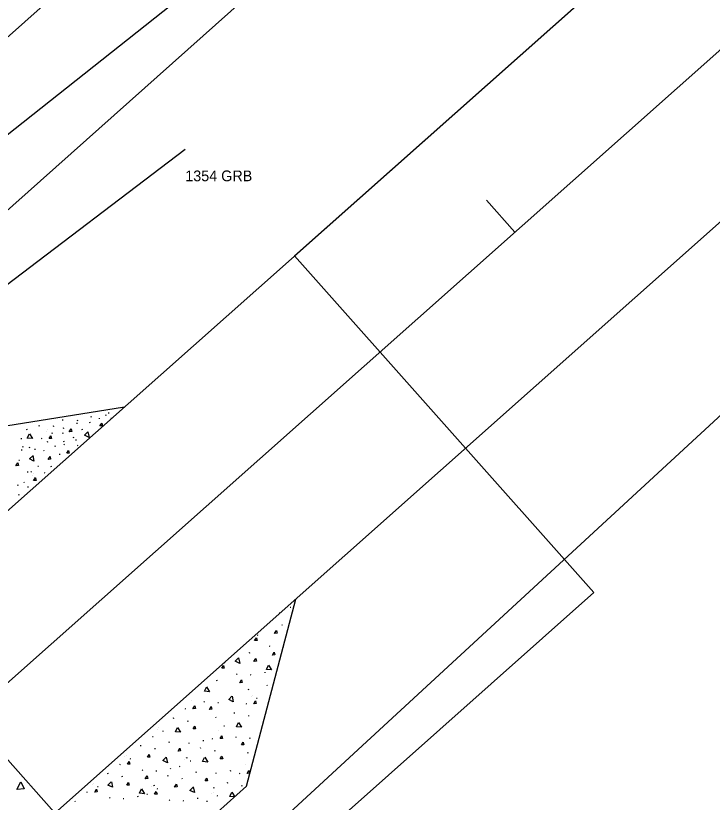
# Model space of a CAD drawing. Extents: x 50001 to 56005, y 49075 to 53926.
# Drawn here: x 53943.1 to 54007.9, y 51854.2 to 51927.5 of the extents above; entities that cross this region are included whole.
import ezdxf

# ---------------------------------------------------------------- set-up
doc = ezdxf.new("R2010")
doc.units = 0
for name, color, linetype in [('Level 1', 7, 'Continuous'), ('Level 11', 7, 'Continuous'), ('Level 12', 7, 'Continuous'), ('Level 15', 7, 'Continuous'), ('Level 18', 7, 'Continuous'), ('Level 19', 7, 'Continuous'), ('Level 20', 7, 'Continuous'), ('Level 3', 7, 'Continuous'), ('Level 57', 7, 'Continuous'), ('Level 7', 7, 'Continuous'), ('Level 8', 7, 'Continuous')]:
    doc.layers.add(name, color=color, linetype=linetype)

msp = doc.modelspace()

# ---------------------------------------------------------------- linework, layer by layer
at = {"layer": 'Level 1'}
for p, q in [((52544.807, 50683.302), (55534.583, 53340.862)), ((52714.147, 50773.616), (54181.768, 52078.16))]:
    msp.add_line(p, q, dxfattribs=at)
at = {"layer": 'Level 11'}
msp.add_line((53944.235, 51830.768), (54450.301, 52297.6), dxfattribs=at)
at = {"layer": 'Level 12'}
for p, q in [((55279.532, 53069.998), (53969.027, 51905.114)), ((53996.93, 51873.722), (53969.027, 51905.114)), ((53681.554, 51593.39), (53996.93, 51873.722))]:
    msp.add_line(p, q, dxfattribs=at)
at = {"layer": 'Level 15'}
msp.add_line((53924.129, 51878.584), (53953.361, 51845.698), dxfattribs=at)
msp.add_lwpolyline([(53943.175, 51855.366), (53943.549, 51856.073), (53943.841, 51855.421), (53943.189, 51855.366)], dxfattribs=at)
at = {"layer": 'Level 18'}
msp.add_line((53926.024, 51903.545), (53965.282, 51934.64), dxfattribs=at)
at = {"layer": 'Level 19'}
for p, q in [((52714.147, 50773.616), (54181.768, 52078.16)), ((53989.569, 51907.317), (53986.911, 51910.307))]:
    msp.add_line(p, q, dxfattribs=at)
at = {"layer": 'Level 20'}
for p, q in [((53930.772, 51871.11), (54173.796, 52087.129)), ((53946.717, 51853.172), (54189.74, 52069.191))]:
    msp.add_line(p, q, dxfattribs=at)
at = {"layer": 'Level 3'}
msp.add_line((53898.742, 51870.567), (54083.389, 52035.124), dxfattribs=at)
at = {"layer": 'Level 7'}
msp.add_line((53922.854, 51887.665), (53958.852, 51915.059), dxfattribs=at)
at = {"layer": 'Level 8'}
for p, q in [((53935.625, 51888.219), (53953.195, 51891.04)), ((53947.407, 51889.839), (53947.431, 51889.752)), ((53948.779, 51889.828), (53948.803, 51889.74)), ((53950.065, 51890.146), (53950.09, 51890.058)), ((53950.818, 51889.99), (53950.842, 51889.902)), ((53951.433, 51890.314), (53951.458, 51890.226)), ((53951.692, 51890.508), (53951.717, 51890.42)), ((53951.98, 51889.935), (53951.916, 51889.955)), ((53945.205, 51889.332), (53945.23, 51889.244)), ((53946.545, 51889.277), (53946.569, 51889.189)), ((53947.471, 51889.1), (53947.496, 51889.012)), ((53948.738, 51889.545), (53948.763, 51889.458)), ((53949.944, 51889.633), (53949.968, 51889.545)), ((53944.059, 51888.987), (53944.083, 51888.9)), ((53945.937, 51888.773), (53945.937, 51888.773)), ((53946.066, 51888.879), (53946.066, 51888.879)), ((53946.503, 51888.557), (53946.439, 51888.576)), ((53947.419, 51888.629), (53947.443, 51888.541)), ((53949.232, 51888.985), (53949.256, 51888.897)), ((53943.554, 51888.096), (53943.578, 51888.008)), ((53945.519, 51888.053), (53945.456, 51888.072)), ((53945.994, 51887.819), (53946.019, 51887.731)), ((53947.516, 51887.851), (53947.54, 51887.763)), ((53948.422, 51888.24), (53948.447, 51888.152)), ((53948.649, 51887.981), (53948.673, 51887.893)), ((53943.586, 51887.059), (53943.611, 51886.971)), ((53943.696, 51887.365), (53943.72, 51887.277)), ((53944.317, 51887.299), (53944.341, 51887.211)), ((53944.829, 51887.106), (53944.853, 51887.018)), ((53945.649, 51887.005), (53945.673, 51886.917)), ((53946.707, 51887.43), (53946.731, 51887.342)), ((53947.604, 51887.486), (53947.544, 51887.545)), ((53948.89, 51887.395), (53948.826, 51887.414)), ((53947.127, 51886.652), (53947.152, 51886.564)), ((53943.413, 51886.016), (53943.349, 51886.035)), ((53945.106, 51885.514), (53945.17, 51885.497)), ((53946.378, 51885.404), (53946.351, 51885.491)), ((53944.139, 51884.98), (53944.204, 51884.962)), ((53944.515, 51884.945), (53944.455, 51885.004)), ((53944.711, 51884.781), (53944.711, 51884.781)), ((53945.801, 51884.854), (53945.737, 51884.873)), ((53943.822, 51884.056), (53943.847, 51883.968)), ((53944.586, 51884.671), (53944.586, 51884.671)), ((53944.878, 51884.372), (53944.851, 51884.459)), ((53943.276, 51883.669), (53943.249, 51883.756)), ((53944.178, 51883.602), (53944.203, 51883.514)), ((53943.37, 51882.767), (53943.343, 51882.854)), ((53964.572, 51855.663), (53969.139, 51873.103)), ((53968.685, 51872.317), (53968.621, 51872.336)), ((53967.709, 51871.799), (53967.645, 51871.817)), ((53967.855, 51870.753), (53967.88, 51870.665)), ((53965.634, 51869.73), (53965.57, 51869.749)), ((53966.752, 51868.677), (53966.691, 51868.734)), ((53968.039, 51868.605), (53967.975, 51868.623)), ((53964.804, 51868.166), (53964.829, 51868.078)), ((53962.583, 51867.143), (53962.519, 51867.162)), ((53963.701, 51866.09), (53963.64, 51866.147)), ((53964.988, 51866.018), (53964.924, 51866.036)), ((53966.253, 51866.314), (53966.278, 51866.226)), ((53961.753, 51865.579), (53961.779, 51865.491)), ((53966.446, 51865.134), (53966.472, 51865.047)), ((53964.718, 51864.734), (53964.744, 51864.646)), ((53959.446, 51863.684), (53959.446, 51863.684)), ((53960.65, 51863.503), (53960.589, 51863.56)), ((53961.937, 51863.43), (53961.873, 51863.449)), ((53964.993, 51864.046), (53964.993, 51864.046)), ((53965.12, 51864.154), (53965.12, 51864.154)), ((53965.562, 51863.838), (53965.497, 51863.856)), ((53958.912, 51862.85), (53958.847, 51862.868)), ((53964.586, 51863.32), (53964.522, 51863.338)), ((53957.721, 51862.077), (53957.747, 51861.99)), ((53961.668, 51862.147), (53961.693, 51862.059)), ((53963.395, 51862.547), (53963.421, 51862.46)), ((53964.731, 51862.273), (53964.757, 51862.186)), ((53959.057, 51861.803), (53959.083, 51861.716)), ((53962.511, 51861.251), (53962.447, 51861.269)), ((53956.268, 51860.989), (53956.268, 51860.989)), ((53956.395, 51861.097), (53956.395, 51861.097)), ((53956.836, 51860.781), (53956.772, 51860.799)), ((53961.971, 51860.897), (53961.971, 51860.897)), ((53955.861, 51860.263), (53955.797, 51860.281)), ((53957.324, 51859.836), (53957.349, 51859.749)), ((53960.506, 51859.952), (53960.531, 51859.864)), ((53961.437, 51860.063), (53961.373, 51860.081)), ((53963.629, 51860.197), (53963.568, 51860.255)), ((53964.916, 51860.125), (53964.852, 51860.144)), ((53954.67, 51859.49), (53954.696, 51859.403)), ((53956.006, 51859.216), (53956.032, 51859.129)), ((53959.241, 51859.655), (53959.177, 51859.674)), ((53960.246, 51859.291), (53960.272, 51859.203)), ((53953.217, 51858.402), (53953.217, 51858.402)), ((53953.344, 51858.51), (53953.344, 51858.51)), ((53958.92, 51858.31), (53958.92, 51858.31)), ((53958.971, 51858.372), (53958.997, 51858.284)), ((53961.582, 51859.017), (53961.608, 51858.929)), ((53964.646, 51858.842), (53964.672, 51858.754)), ((53952.81, 51857.676), (53952.746, 51857.694)), ((53953.785, 51858.194), (53953.721, 51858.212)), ((53958.793, 51858.202), (53958.793, 51858.202)), ((53959.361, 51857.994), (53959.297, 51858.013)), ((53964.496, 51857.657), (53964.496, 51857.657)), ((53951.619, 51856.903), (53951.645, 51856.816)), ((53954.903, 51857.14), (53954.842, 51857.198)), ((53956.19, 51857.068), (53956.126, 51857.087)), ((53957.455, 51857.365), (53957.481, 51857.277)), ((53958.386, 51857.476), (53958.322, 51857.494)), ((53959.849, 51857.05), (53959.875, 51856.962)), ((53961.766, 51856.868), (53961.702, 51856.887)), ((53963.031, 51857.165), (53963.057, 51857.077)), ((53963.962, 51856.822), (53963.898, 51856.841)), ((53952.955, 51856.629), (53952.981, 51856.542)), ((53957.195, 51856.703), (53957.221, 51856.616)), ((53958.531, 51856.43), (53958.557, 51856.342)), ((53950.166, 51855.815), (53950.166, 51855.815)), ((53950.293, 51855.923), (53950.293, 51855.923)), ((53950.735, 51855.607), (53950.67, 51855.626)), ((53953.361, 51845.698), (53964.572, 51855.663)), ((53955.742, 51855.615), (53955.742, 51855.615)), ((53955.869, 51855.723), (53955.869, 51855.723)), ((53955.921, 51855.785), (53955.946, 51855.697)), ((53956.311, 51855.407), (53956.246, 51855.426)), ((53961.497, 51855.585), (53961.522, 51855.497)), ((53962.771, 51856.05), (53962.797, 51855.963)), ((53964.107, 51855.776), (53964.133, 51855.689)), ((53949.759, 51855.089), (53949.695, 51855.107)), ((53954.404, 51854.778), (53954.43, 51854.69)), ((53955.335, 51854.889), (53955.271, 51854.907)), ((53961.318, 51854.962), (53961.318, 51854.962)), ((53961.445, 51855.07), (53961.445, 51855.07)), ((53961.886, 51854.754), (53961.822, 51854.772)), ((53948.568, 51854.316), (53948.594, 51854.229)), ((53951.852, 51854.553), (53951.791, 51854.611)), ((53953.139, 51854.481), (53953.075, 51854.5)), ((53957.428, 51854.353), (53957.367, 51854.411)), ((53958.715, 51854.281), (53958.651, 51854.3)), ((53959.98, 51854.578), (53960.006, 51854.49)), ((53960.911, 51854.235), (53960.847, 51854.254))]:
    msp.add_line(p, q, dxfattribs=at)
for points in [[(53951.077, 51889.504), (53951.138, 51889.255), (53950.907, 51889.245), (53951.077, 51889.504)], [(53944.334, 51888.526), (53944.613, 51888.071), (53944.14, 51888.125), (53944.329, 51888.518)], [(53948.222, 51888.974), (53948.283, 51888.725), (53948.052, 51888.714), (53948.222, 51888.974)], [(53949.792, 51888.698), (53949.899, 51888.175), (53949.473, 51888.387), (53949.785, 51888.692)], [(53946.345, 51888.343), (53946.406, 51888.094), (53946.175, 51888.084), (53946.345, 51888.343)], [(53947.987, 51886.963), (53948.049, 51886.714), (53947.818, 51886.704), (53947.987, 51886.963)], [(53944.655, 51886.483), (53944.762, 51885.96), (53944.336, 51886.172), (53944.648, 51886.477)], [(53946.253, 51886.393), (53946.314, 51886.144), (53946.083, 51886.133), (53946.253, 51886.393)], [(53943.255, 51885.802), (53943.316, 51885.553), (53943.085, 51885.543), (53943.255, 51885.802)], [(53944.898, 51884.423), (53944.959, 51884.174), (53944.728, 51884.163), (53944.898, 51884.423)], [(53967.347, 51870.173), (53967.412, 51869.925), (53967.181, 51869.911), (53967.347, 51870.173)], [(53965.479, 51869.515), (53965.544, 51869.266), (53965.313, 51869.253), (53965.479, 51869.515)], [(53967.143, 51868.16), (53967.208, 51867.912), (53966.977, 51867.898), (53967.143, 51868.16)], [(53963.818, 51867.629), (53963.933, 51867.107), (53963.503, 51867.313), (53963.811, 51867.623)], [(53965.417, 51867.563), (53965.482, 51867.315), (53965.251, 51867.301), (53965.417, 51867.563)], [(53962.428, 51866.928), (53962.493, 51866.679), (53962.263, 51866.666), (53962.428, 51866.928)], [(53966.615, 51866.96), (53966.901, 51866.509), (53966.427, 51866.556), (53966.61, 51866.952)], [(53960.833, 51864.924), (53961.119, 51864.473), (53960.645, 51864.52), (53960.828, 51864.916)], [(53964.092, 51865.573), (53964.157, 51865.325), (53963.926, 51865.311), (53964.092, 51865.573)], [(53963.214, 51864.064), (53963.328, 51863.543), (53962.899, 51863.749), (53963.206, 51864.058)], [(53965.407, 51863.622), (53965.472, 51863.374), (53965.241, 51863.36), (53965.407, 51863.622)], [(53959.732, 51863.152), (53959.797, 51862.904), (53959.566, 51862.89), (53959.732, 51863.152)], [(53961.275, 51863.091), (53961.34, 51862.843), (53961.109, 51862.83), (53961.275, 51863.091)], [(53959.75, 51861.269), (53959.815, 51861.021), (53959.584, 51861.007), (53959.75, 51861.269)], [(53963.811, 51861.618), (53964.097, 51861.168), (53963.623, 51861.215), (53963.807, 51861.61)], [(53958.137, 51861.148), (53958.423, 51860.698), (53957.949, 51860.745), (53958.132, 51861.141)], [(53962.257, 51860.365), (53962.322, 51860.117), (53962.092, 51860.103), (53962.257, 51860.365)], [(53964.253, 51859.786), (53964.318, 51859.538), (53964.087, 51859.524), (53964.253, 51859.786)], [(53958.345, 51859.21), (53958.41, 51858.962), (53958.179, 51858.949), (53958.345, 51859.21)], [(53955.498, 51858.637), (53955.563, 51858.389), (53955.332, 51858.375), (53955.498, 51858.637)], [(53957.072, 51858.385), (53957.187, 51857.863), (53956.758, 51858.069), (53957.065, 51858.379)], [(53960.662, 51858.362), (53960.948, 51857.911), (53960.474, 51857.958), (53960.657, 51858.354)], [(53962.275, 51858.482), (53962.34, 51858.234), (53962.109, 51858.22), (53962.275, 51858.482)], [(53953.631, 51857.978), (53953.696, 51857.73), (53953.465, 51857.716), (53953.631, 51857.978)], [(53964.783, 51857.125), (53964.847, 51856.877), (53964.617, 51856.863), (53964.783, 51857.125)], [(53955.294, 51856.624), (53955.359, 51856.375), (53955.128, 51856.362), (53955.294, 51856.624)], [(53960.87, 51856.424), (53960.935, 51856.176), (53960.704, 51856.162), (53960.87, 51856.424)], [(53950.58, 51855.391), (53950.645, 51855.143), (53950.414, 51855.129), (53950.58, 51855.391)], [(53951.97, 51856.092), (53952.084, 51855.571), (53951.655, 51855.777), (53951.963, 51856.086)], [(53953.568, 51856.027), (53953.633, 51855.779), (53953.402, 51855.765), (53953.568, 51856.027)], [(53954.766, 51855.423), (53955.052, 51854.973), (53954.578, 51855.019), (53954.762, 51855.415)], [(53958.023, 51855.85), (53958.088, 51855.602), (53957.857, 51855.588), (53958.023, 51855.85)], [(53959.597, 51855.598), (53959.712, 51855.077), (53959.283, 51855.283), (53959.59, 51855.592)], [(53956.156, 51855.191), (53956.221, 51854.943), (53955.99, 51854.93), (53956.156, 51855.191)], [(53963.187, 51855.121), (53963.473, 51854.671), (53962.999, 51854.717), (53963.182, 51855.113)]]:
    msp.add_lwpolyline(points, dxfattribs=at)

# ---------------------------------------------------------------- texts
at = {"layer": 'Level 57'}
msp.add_text('1354 GRB', height=1, dxfattribs=at).set_placement((53958.852, 51912.059))

doc.saveas('drawing.dxf')
